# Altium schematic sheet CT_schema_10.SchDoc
size 274 x 160 mm
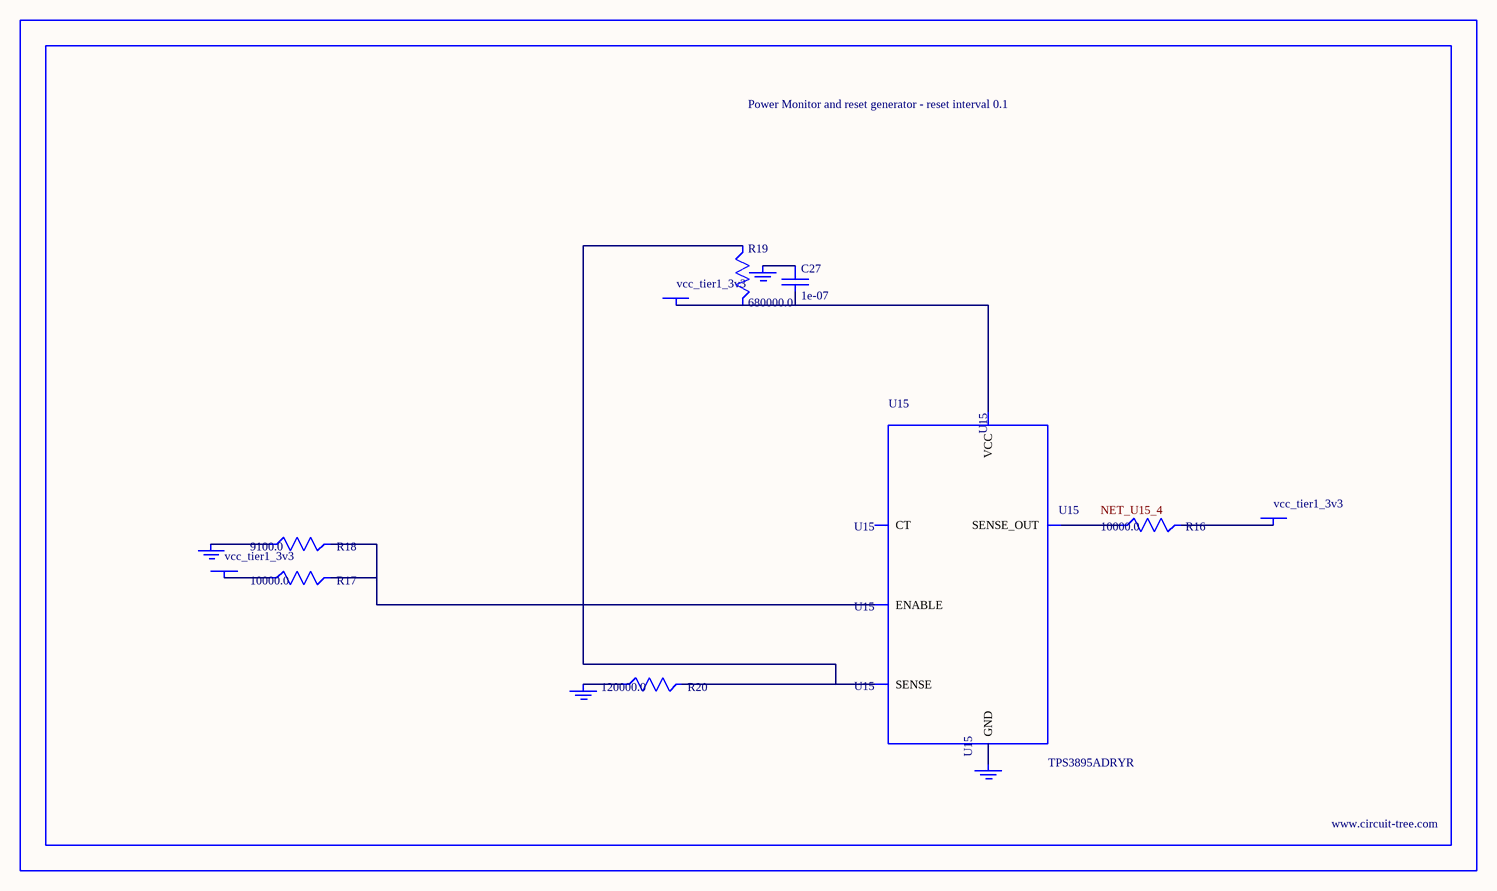
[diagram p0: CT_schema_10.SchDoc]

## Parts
BORDER9  (no value)
C27  1e-07  [C0402]
GND_INSTANCE_9_0  (no value)
GND_INSTANCE_9_1  (no value)
GND_INSTANCE_9_2  (no value)
GND_INSTANCE_9_3  (no value)
POWER_INSTANCE_9_0  vcc_tier1_3v3
POWER_INSTANCE_9_1  vcc_tier1_3v3
POWER_INSTANCE_9_2  vcc_tier1_3v3
R16  10000.0  [R0603]
R17  10000.0  [R0603]
R18  9100.0  [R0603]
R19  680000.0  [R0603]
R20  120000.0  [R0603]
U15  TPS3895ADRYR  [SON-6]

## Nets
NetC27_1: C27.1 GND_INSTANCE_9_2.0(GND)
NetC27_2: C27.2 POWER_INSTANCE_9_2.0(PWR) R19.2 U15.6(VCC)
NetGND_INSTANCE_9_0_0: GND_INSTANCE_9_0.0(GND) R18.1
NetGND_INSTANCE_9_1_0: GND_INSTANCE_9_1.0(GND) R20.1
NetGND_INSTANCE_9_3_0: GND_INSTANCE_9_3.0(GND) U15.2(GND)
NetPOWER_INSTANCE_9_0_0: POWER_INSTANCE_9_0.0(PWR) R17.1
NetPOWER_INSTANCE_9_1_0: POWER_INSTANCE_9_1.0(PWR) R16.2
NetR16_1: R16.1 U15.4(SENSE_OUT)
NetR17_2: R17.2 R18.2 U15.1(ENABLE)
NetR19_1: R19.1 R20.2 U15.3(SENSE)

Not connected (* = marked no-connect by the designer): U15 5(CT)

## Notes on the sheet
- Labels drawn without touching a wire or pin: NET_U15_4

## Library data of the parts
BORDER9 = BORDER_PAGE9
C27 = C0402C104K3RACTU
GND_INSTANCE_9_0-GND_INSTANCE_9_3 = GND
POWER_INSTANCE_9_0-POWER_INSTANCE_9_2 = PWR
R16 R17 = RC0603JR-0710KL
R18 = RC0603JR-079K1L
R19 = RC0603JR-07680KL
R20 = RC0603JR-07120KL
